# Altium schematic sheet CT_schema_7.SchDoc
size 479 x 328 mm
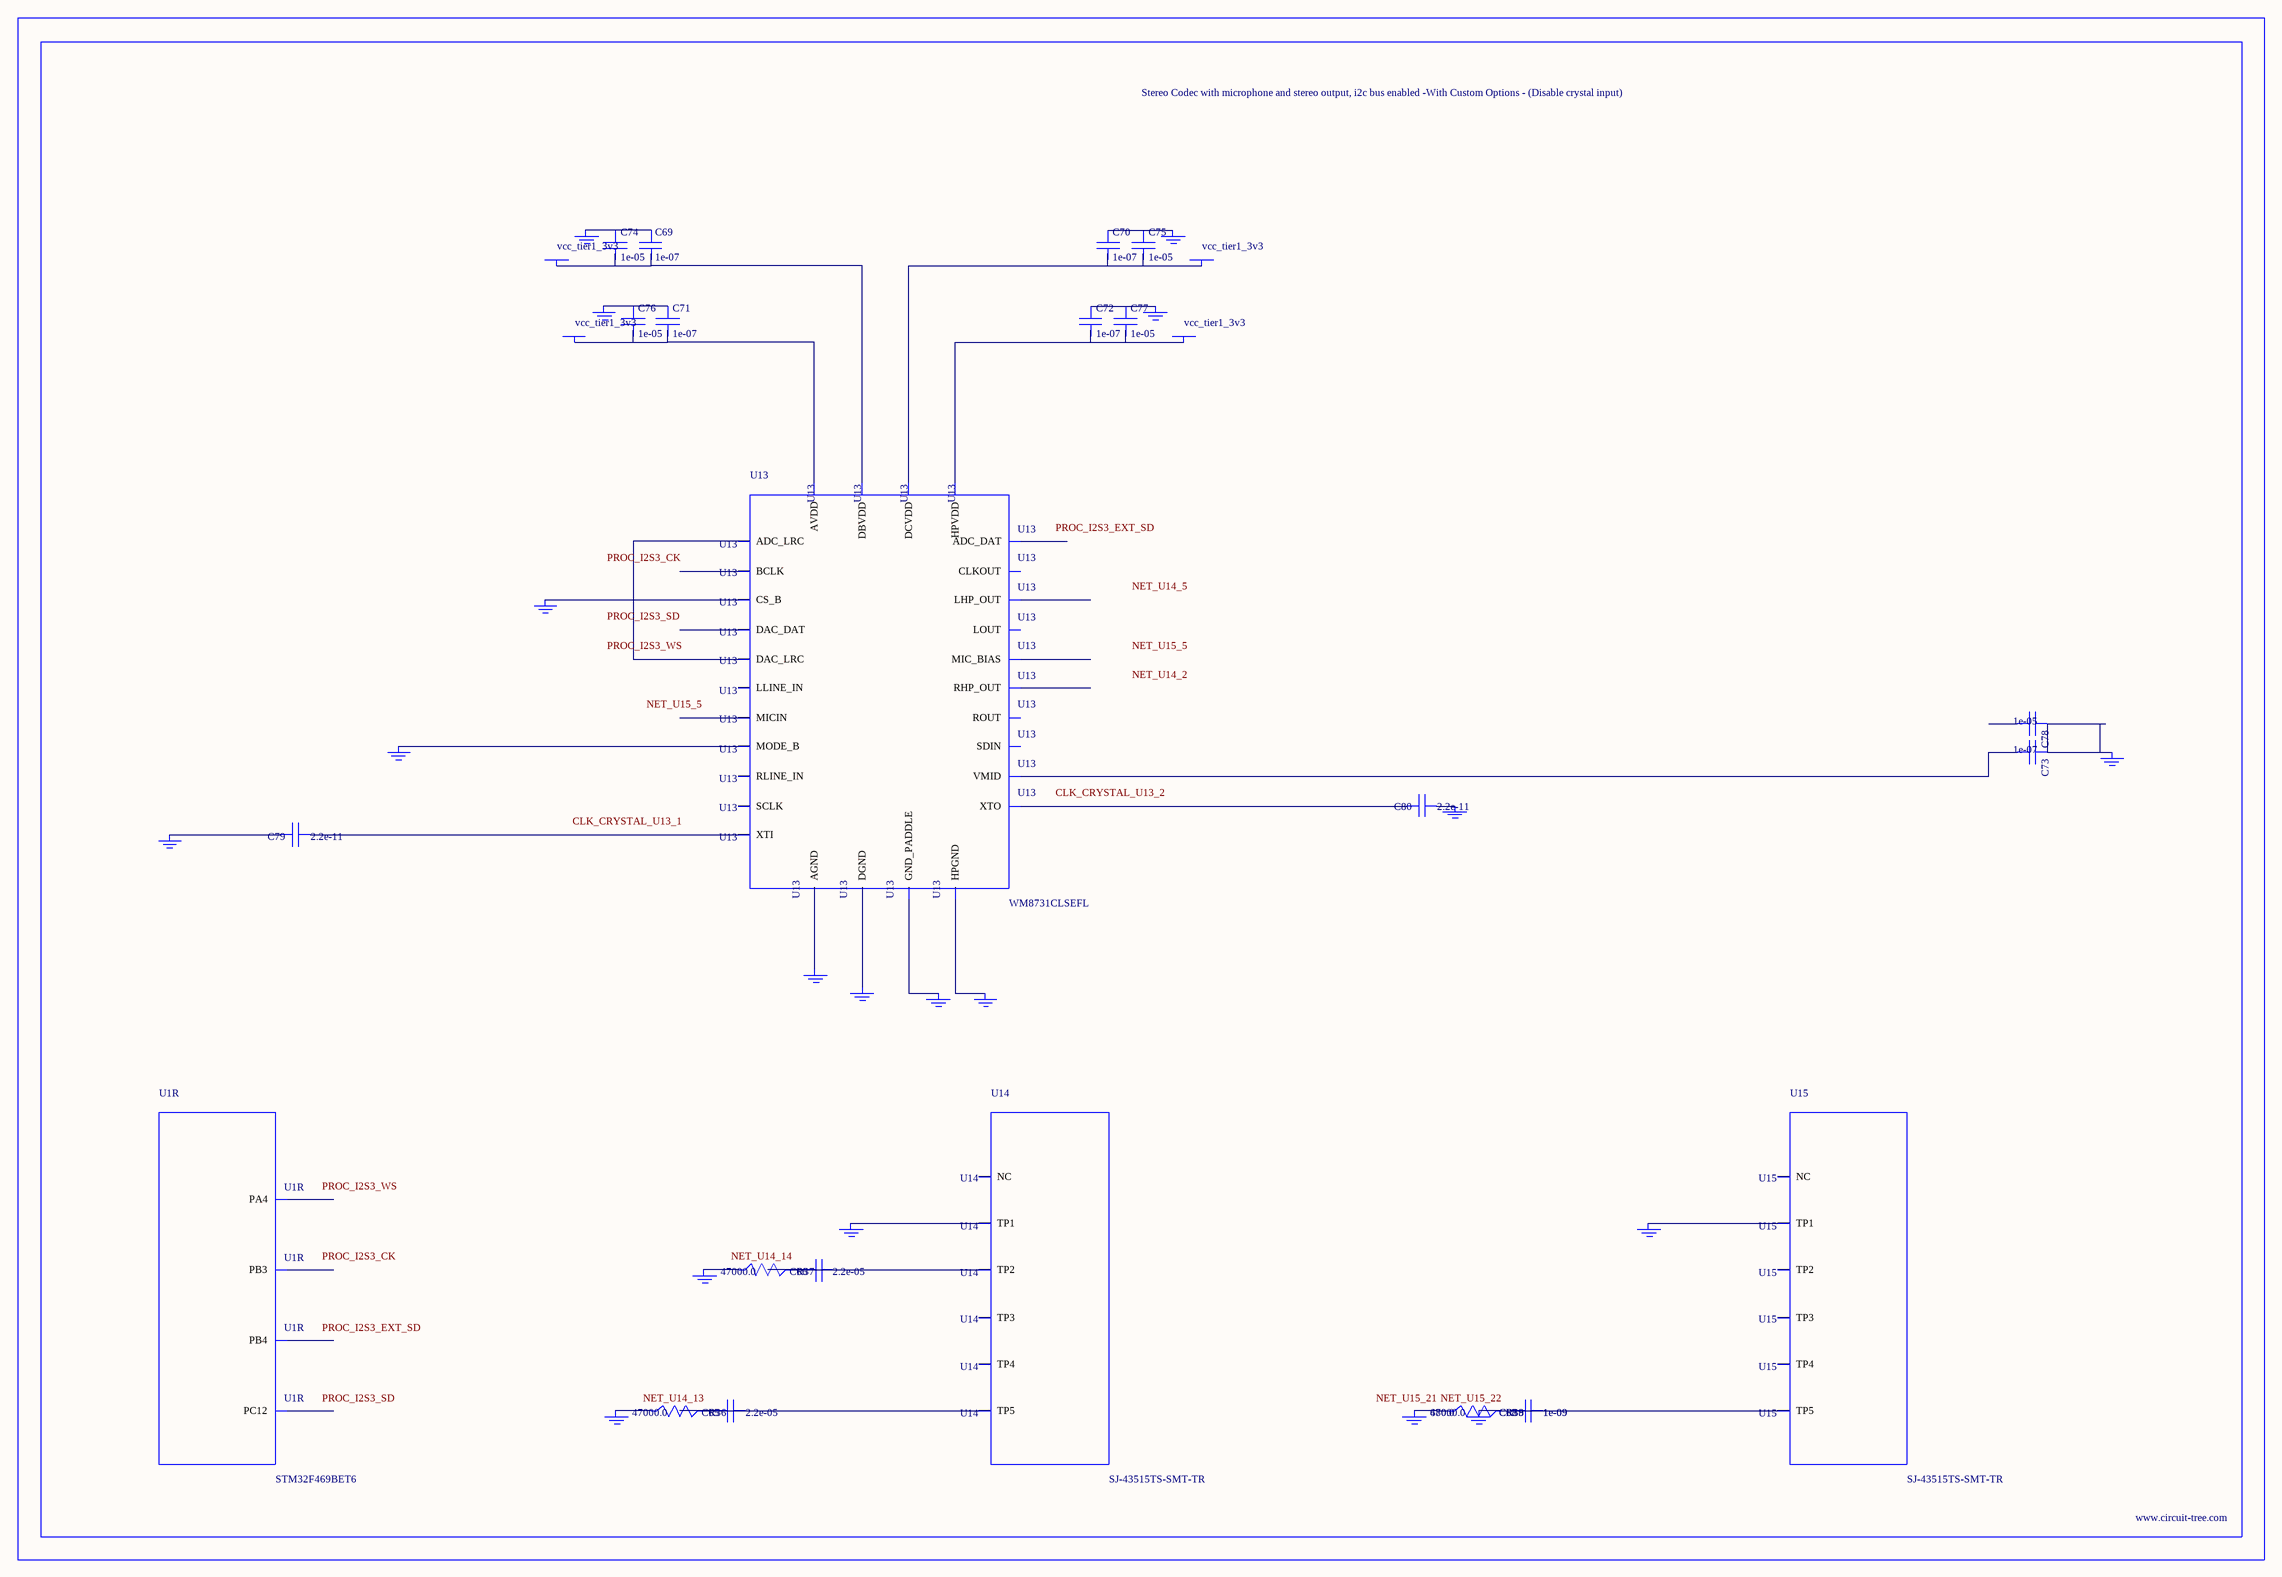
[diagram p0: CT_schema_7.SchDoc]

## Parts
BORDER6  (no value)
C65  2.2e-05  [C1210]
C66  2.2e-05  [C1210]
C67  1e-09  [C0402]
C68  1e-09  [C0402]
C69  1e-07  [C0402]
C70  1e-07  [C0402]
C71  1e-07  [C0402]
C72  1e-07  [C0402]
C73  1e-07  [C0402]
C74  1e-05  [C0805]
C75  1e-05  [C0805]
C76  1e-05  [C0805]
C77  1e-05  [C0805]
C78  1e-05  [C0805]
C79  2.2e-11  [C0402]
C80  2.2e-11  [C0402]
GND_INSTANCE_6_0  (no value)
GND_INSTANCE_6_1  (no value)
GND_INSTANCE_6_2  (no value)
GND_INSTANCE_6_3  (no value)
GND_INSTANCE_6_4  (no value)
GND_INSTANCE_6_5  (no value)
GND_INSTANCE_6_6  (no value)
GND_INSTANCE_6_7  (no value)
GND_INSTANCE_6_8  (no value)
GND_INSTANCE_6_9  (no value)
GND_INSTANCE_6_10  (no value)
GND_INSTANCE_6_11  (no value)
GND_INSTANCE_6_12  (no value)
GND_INSTANCE_6_13  (no value)
GND_INSTANCE_6_14  (no value)
GND_INSTANCE_6_15  (no value)
GND_INSTANCE_6_16  (no value)
GND_INSTANCE_6_17  (no value)
GND_INSTANCE_6_18  (no value)
POWER_INSTANCE_6_0  vcc_tier1_3v3
POWER_INSTANCE_6_1  vcc_tier1_3v3
POWER_INSTANCE_6_2  vcc_tier1_3v3
POWER_INSTANCE_6_3  vcc_tier1_3v3
R36  47000.0  [R0603]
R37  47000.0  [R0603]
R38  47000.0  [R0603]
R39  680.0  [R0603]
U1  STM32F469BET6  [LQFP208]  (part R of 18)
U13  WM8731CLSEFL  [QFN-28]
U14  SJ-43515TS-SMT-TR  [SJ-43515TS-SMT-TR]
U15  SJ-43515TS-SMT-TR  [SJ-43515TS-SMT-TR]

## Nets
NetC65_1: C65.1 C65.2 R36.2 U14.5(TP5)
NetC66_1: C66.1 C66.2 R37.2 U14.2(TP2)
NetC67_1: C67.1 C67.2 C68.1 C68.2 GND_INSTANCE_6_18.0(GND) R38.2 R39.2 U15.5(TP5)
NetC69_1: C69.1 C74.1 GND_INSTANCE_6_3.0(GND)
NetC69_2: C69.2 C74.2 POWER_INSTANCE_6_1.0(PWR) U13.5(DBVDD)
NetC70_1: C70.1 C75.1 GND_INSTANCE_6_2.0(GND)
NetC70_2: C70.2 C75.2 POWER_INSTANCE_6_0.0(PWR) U13.3(DCVDD)
NetC71_1: C71.1 C76.1 GND_INSTANCE_6_6.0(GND)
NetC71_2: C71.2 C76.2 POWER_INSTANCE_6_3.0(PWR) U13.18(AVDD)
NetC72_1: C72.1 C77.1 GND_INSTANCE_6_4.0(GND)
NetC72_2: C72.2 C77.2 POWER_INSTANCE_6_2.0(PWR) U13.12(HPVDD)
NetC73_1: C73.1 C78.1 GND_INSTANCE_6_7.0(GND)
NetC73_2: C73.2 U13.20(VMID)
NetC79_1: C79.1 U13.1(XTI)
NetC79_2: C79.2 GND_INSTANCE_6_0.0(GND)
NetC80_1: C80.1 GND_INSTANCE_6_1.0(GND)
NetC80_2: C80.2 U13.2(XTO)
NetGND_INSTANCE_6_5_0: GND_INSTANCE_6_5.0(GND) U13.15(HPGND)
NetGND_INSTANCE_6_8_0: GND_INSTANCE_6_8.0(GND) U13.25(MODE_B)
NetGND_INSTANCE_6_9_0: GND_INSTANCE_6_9.0(GND) U13.26(CS_B)
NetGND_INSTANCE_6_10_0: GND_INSTANCE_6_10.0(GND) U13.29(GND_PADDLE)
NetGND_INSTANCE_6_11_0: GND_INSTANCE_6_11.0(GND) U13.4(DGND)
NetGND_INSTANCE_6_12_0: GND_INSTANCE_6_12.0(GND) U13.19(AGND)
NetGND_INSTANCE_6_13_0: GND_INSTANCE_6_13.0(GND) U14.1(TP1)
NetGND_INSTANCE_6_14_0: GND_INSTANCE_6_14.0(GND) R37.1
NetGND_INSTANCE_6_15_0: GND_INSTANCE_6_15.0(GND) R36.1
NetGND_INSTANCE_6_16_0: GND_INSTANCE_6_16.0(GND) U15.1(TP1)
NetGND_INSTANCE_6_17_0: GND_INSTANCE_6_17.0(GND) R38.1 R39.1
NetU13_9: U13.9(DAC_LRC) U13.11(ADC_LRC)

Not connected (* = marked no-connect by the designer): C78 2; U1 53(PA4) 163(PC12) 192(PB3) 193(PB4); U13 6(CLKOUT) 7(BCLK) 8(DAC_DAT) 10(ADC_DAT) 13(LHP_OUT) 14(RHP_OUT) 16(LOUT) 17(ROUT) 21(MIC_BIAS) 22(MICIN) 23(RLINE_IN) 24(LLINE_IN) 27(SDIN) 28(SCLK); U14 3(TP3) 4(TP4) 6(NC); U15 2(TP2) 3(TP3) 4(TP4) 6(NC)

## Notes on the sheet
- Labels drawn without touching a wire or pin: CLK_CRYSTAL_U13_1, CLK_CRYSTAL_U13_2, NET_U14_2, NET_U14_5, NET_U14_13, NET_U14_14, NET_U15_5, NET_U15_21, NET_U15_22, PROC_I2S3_CK, PROC_I2S3_EXT_SD, PROC_I2S3_SD, PROC_I2S3_WS

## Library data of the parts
BORDER6 = BORDER_PAGE6
C65 C66 = C1210C224K5RACTU
C67 C68 = C0402C102K3RAC
C69-C73 = C0402C104K3RACTU
C74-C78 = C0805C106K8RACTU
C79 C80 = C0402C220K3RAC
GND_INSTANCE_6_0-GND_INSTANCE_6_18 = GND
POWER_INSTANCE_6_0-POWER_INSTANCE_6_3 = PWR
R36-R38 = RC0603JR-0747KL
R39 = RC0603JR-07680RL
